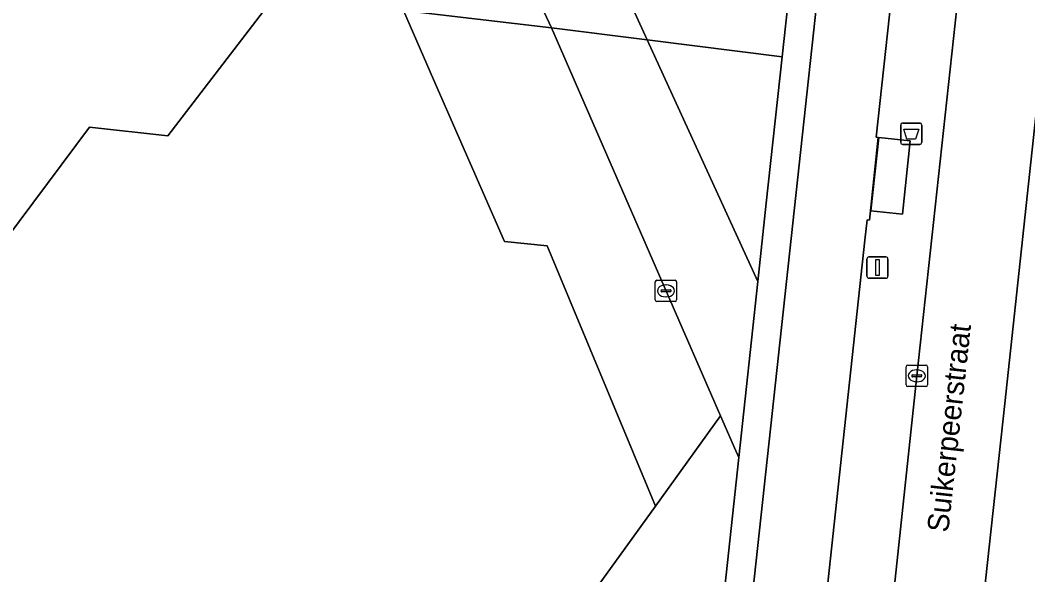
# Model space of a CAD drawing. Extents: x 162026 to 163502, y 387295 to 388169.
# Drawn here: x 162307.77 to 162355.04, y 387456.66 to 387482.7 of the extents above; entities that cross this region are included whole.
import ezdxf

# ---------------------------------------------------------------- set-up
doc = ezdxf.new("R2010")
doc.units = 0
for name, color, linetype in [('IMGEO_Afvalbak', 7, 'Continuous'), ('IMGEO_Berm_groen', 7, 'Continuous'), ('IMGEO_Erf', 7, 'Continuous'), ('IMGEO_Fietspad_gesloten', 7, 'Continuous'), ('IMGEO_Kolk', 7, 'Continuous'), ('IMGEO_Lichtmast', 7, 'Continuous'), ('IMGEO_Openbare_ruimte_label', 7, 'Continuous'), ('IMGEO_Pand', 7, 'Continuous'), ('IMGEO_Rijbaan_lokaal_gesloten', 7, 'Continuous'), ('IMGEO_Rijbaan_lokaal_open', 7, 'Continuous'), ('IMGEO_Voetpad_open', 7, 'Continuous')]:
    doc.layers.add(name, color=color, linetype=linetype)

msp = doc.modelspace()

# ---------------------------------------------------------------- linework, layer by layer
at = {"layer": 'IMGEO_Afvalbak'}
for p, q in [((162349.077, 387476.972), (162349.077, 387477.772)), ((162349.077, 387477.772), (162349.077, 387476.972)), ((162349.177, 387477.872), (162349.967, 387477.872)), ((162349.967, 387477.872), (162349.177, 387477.872)), ((162350.067, 387477.772), (162350.067, 387476.972)), ((162350.067, 387476.972), (162350.067, 387477.772)), ((162349.967, 387476.872), (162349.177, 387476.872)), ((162349.177, 387476.872), (162349.967, 387476.872))]:
    msp.add_line(p, q, dxfattribs=at)
msp.add_lwpolyline([(162349.22, 387477.586), (162349.924, 387477.586), (162349.775, 387477.116), (162349.369, 387477.116), (162349.22, 387477.586)], dxfattribs=at)
for centre, start, end in [((162349.177, 387477.772), 90, 180), ((162349.177, 387477.772), 90, 180), ((162349.967, 387477.772), 0, 90), ((162349.967, 387477.772), 360, 90), ((162349.177, 387476.972), 180, 270), ((162349.177, 387476.972), 180, 270), ((162349.967, 387476.972), 270, 0), ((162349.967, 387476.972), 270, 0)]:
    msp.add_arc(centre, 0.1, start, end, dxfattribs=at)
at = {"layer": 'IMGEO_Berm_groen'}
for points in [[(162367.963, 387504.443), (162368.74, 387511.448), (162359.196, 387512.511), (162358.952, 387511.213), (162358.817, 387510.216), (162358.349, 387505.53), (162353.961, 387464.714), (162349.86, 387427.109)], [(162335.741, 387484.94), (162337.187, 387481.776), (162343.514, 387480.982), (162344.456, 387489.614)]]:
    msp.add_lwpolyline(points, dxfattribs=at)
msp.add_lwpolyline([(162343.514, 387480.982), (162337.187, 387481.776), (162342.369, 387470.441), (162342.765, 387474.112)], close=True, dxfattribs=at)
at = {"layer": 'IMGEO_Erf'}
msp.add_lwpolyline([(162332.69, 387482.34), (162325.748, 387483.156), (162327.164, 387479.918), (162330.488, 387472.319), (162332.494, 387472.101), (162337.569, 387459.89), (162340.618, 387464.132)], close=True, dxfattribs=at)
at = {"layer": 'IMGEO_Fietspad_gesloten'}
msp.add_lwpolyline([(162346.258, 387493.792), (162342.37, 387458.038), (162338.712, 387424.373), (162342.502, 387427.016), (162347.393, 387472.381), (162347.51, 387473.321), (162347.617, 387473.315), (162348.021, 387477.193), (162347.927, 387477.213), (162350.067, 387496.885), (162350.106, 387497.113)], dxfattribs=at)
at = {"layer": 'IMGEO_Kolk'}
for p, q in [((162337.566, 387469.568), (162337.566, 387470.42)), ((162337.641, 387470.494), (162338.493, 387470.494)), ((162337.868, 387470.037), (162338.266, 387470.037)), ((162338.054, 387470.274), (162338.079, 387470.274)), ((162338.567, 387470.42), (162338.567, 387469.568)), ((162337.825, 387469.988), (162337.825, 387470)), ((162338.263, 387469.951), (162337.865, 387469.951)), ((162338.077, 387469.714), (162338.052, 387469.714)), ((162338.309, 387470), (162338.309, 387469.988)), ((162338.493, 387469.494), (162337.641, 387469.494)), ((162349.333, 387465.58), (162349.333, 387466.432)), ((162349.408, 387466.506), (162350.26, 387466.506)), ((162349.821, 387466.286), (162349.846, 387466.286)), ((162350.334, 387466.432), (162350.334, 387465.58)), ((162349.592, 387466), (162349.592, 387466.012)), ((162350.03, 387465.963), (162349.632, 387465.963)), ((162349.635, 387466.049), (162350.033, 387466.049)), ((162350.076, 387466.012), (162350.076, 387466)), ((162350.26, 387465.506), (162349.408, 387465.506)), ((162349.844, 387465.726), (162349.819, 387465.726))]:
    msp.add_line(p, q, dxfattribs=at)
for points in [[(162337.566, 387469.568), (162337.566, 387470.42)], [(162337.641, 387470.494), (162338.493, 387470.494)], [(162338.567, 387470.42), (162338.567, 387469.568)], [(162338.493, 387469.494), (162337.641, 387469.494)], [(162349.333, 387465.58), (162349.333, 387466.432)], [(162349.408, 387466.506), (162350.26, 387466.506)], [(162350.334, 387466.432), (162350.334, 387465.58)], [(162350.26, 387465.506), (162349.408, 387465.506)]]:
    msp.add_lwpolyline(points, dxfattribs=at)
for centre, radius, start, end in [((162337.643, 387470.418), 0.0765, 91.552, 178.448), ((162337.643, 387470.418), 0.0765, 91.552, 178.448), ((162337.865, 387469.997), 0.0403, 85.8775, 175.7526), ((162338.27, 387469.999), 0.0386, 1.7309, 96.639), ((162338.491, 387470.418), 0.0765, 1.552, 88.448), ((162338.491, 387470.418), 0.0765, 1.552, 88.448), ((162337.643, 387469.57), 0.0765, 181.552, 268.448), ((162337.643, 387469.57), 0.0765, 181.552, 268.448), ((162337.862, 387469.987), 0.0366, 178.938, 274.7102), ((162338.266, 387469.994), 0.043, 264.8664, 352.4533), ((162338.491, 387469.57), 0.0765, 271.552, 358.448), ((162338.491, 387469.57), 0.0765, 271.552, 358.448), ((162349.41, 387466.43), 0.0765, 91.552, 178.448), ((162349.41, 387466.43), 0.0765, 91.552, 178.448), ((162350.258, 387466.43), 0.0765, 1.552, 88.448), ((162350.258, 387466.43), 0.0765, 1.552, 88.448), ((162349.632, 387466.009), 0.0403, 85.8775, 175.7526), ((162349.629, 387465.999), 0.0366, 178.938, 274.7102), ((162350.033, 387466.006), 0.043, 264.8664, 352.4533), ((162350.037, 387466.011), 0.0386, 1.7309, 96.639), ((162349.41, 387465.582), 0.0765, 181.552, 268.448), ((162349.41, 387465.582), 0.0765, 181.552, 268.448), ((162350.258, 387465.582), 0.0765, 271.552, 358.448), ((162350.258, 387465.582), 0.0765, 271.552, 358.448)]:
    msp.add_arc(centre, radius, start, end, dxfattribs=at)
for centre, major_axis, ratio, start_param, end_param in [((162338.053, 387469.994), (-0.387, 0.002), 0.722429, 4.712389, 7.853982), ((162338.078, 387469.994), (-0.39, 0.002), 0.717154, 1.570796, 4.712389), ((162349.82, 387466.006), (-0.387, 0.002), 0.722429, 4.712389, 7.853982), ((162349.845, 387466.006), (-0.39, 0.002), 0.717154, 1.570796, 4.712389)]:
    msp.add_ellipse(centre, major_axis=major_axis, ratio=ratio, start_param=start_param, end_param=end_param, dxfattribs=at)
at = {"layer": 'IMGEO_Lichtmast'}
for p, q in [((162347.489, 387470.686), (162347.489, 387471.486)), ((162347.489, 387471.486), (162347.489, 387470.686)), ((162347.589, 387471.586), (162348.379, 387471.586)), ((162348.379, 387471.586), (162347.589, 387471.586)), ((162348.479, 387471.486), (162348.479, 387470.686)), ((162348.479, 387470.686), (162348.479, 387471.486)), ((162348.379, 387470.586), (162347.589, 387470.586)), ((162347.589, 387470.586), (162348.379, 387470.586))]:
    msp.add_line(p, q, dxfattribs=at)
msp.add_lwpolyline([(162347.909, 387471.461), (162348.059, 387471.461), (162348.059, 387470.711), (162347.909, 387470.711), (162347.909, 387471.461)], dxfattribs=at)
for centre, start, end in [((162347.589, 387471.486), 90, 180), ((162347.589, 387471.486), 90, 180), ((162348.379, 387471.486), 0, 90), ((162348.379, 387471.486), 360, 90), ((162347.589, 387470.686), 180, 270), ((162347.589, 387470.686), 180, 270), ((162348.379, 387470.686), 270, 0), ((162348.379, 387470.686), 270, 0)]:
    msp.add_arc(centre, 0.1, start, end, dxfattribs=at)
at = {"layer": 'IMGEO_Pand'}
msp.add_lwpolyline([(162334.245, 387455.266), (162337.569, 387459.89), (162332.494, 387472.101), (162330.488, 387472.319), (162327.164, 387479.918), (162325.748, 387483.156), (162319.71, 387483.814), (162314.702, 387477.278), (162311.025, 387477.679), (162303.078, 387467.032)], dxfattribs=at)
at = {"layer": 'IMGEO_Rijbaan_lokaal_gesloten'}
msp.add_lwpolyline([(162353.961, 387464.714), (162358.349, 387505.53), (162354.15, 387506.017), (162353.924, 387503.81), (162353.243, 387497.608), (162353.136, 387496.605), (162352.335, 387489.102), (162352.257, 387488.34), (162349.834, 387466.006), (162349.065, 387458.811), (162348.272, 387451.322), (162348.127, 387450.097), (162347.103, 387440.899), (162346.475, 387434.916), (162346.314, 387433.695), (162345.649, 387427.488), (162345.245, 387423.574), (162349.464, 387424), (162349.86, 387427.109)], close=True, dxfattribs=at)
at = {"layer": 'IMGEO_Rijbaan_lokaal_open'}
msp.add_lwpolyline([(162332.51, 387496.328), (162331.324, 387494.702), (162329.045, 387491.322), (162328.998, 387491.247), (162328.958, 387491.169), (162328.925, 387491.087), (162328.9, 387491.003), (162328.882, 387490.916), (162328.873, 387490.829), (162328.87, 387490.741), (162328.876, 387490.653), (162328.89, 387490.566), (162328.911, 387490.481), (162328.94, 387490.397), (162328.96, 387490.351), (162329.102, 387490.046), (162330.706, 387486.601), (162332.69, 387482.34), (162337.187, 387481.776), (162335.741, 387484.94)], dxfattribs=at)
msp.add_lwpolyline([(162337.187, 387481.776), (162332.69, 387482.34), (162340.618, 387464.132), (162341.336, 387462.483), (162341.478, 387462.168), (162342.369, 387470.441)], close=True, dxfattribs=at)
at = {"layer": 'IMGEO_Voetpad_open'}
for points in [[(162342.851, 387499.633), (162315.859, 387502.639), (162318.177, 387500), (162320.407, 387497.461), (162310.872, 387484.483), (162310.539, 387484.029), (162298.229, 387485.888), (162293.758, 387496.206), (162291.762, 387495.313), (162289.996, 387490.573), (162287.708, 387487.29), (162294.112, 387472.505), (162292.215, 387469.541), (162293.144, 387466.992), (162297.036, 387466.568), (162297.706, 387467.617), (162303.078, 387467.032), (162311.025, 387477.679), (162314.702, 387477.278), (162319.71, 387483.814), (162325.748, 387483.156), (162332.69, 387482.34), (162330.706, 387486.601), (162329.102, 387490.046)], [(162349.834, 387466.006), (162352.257, 387488.34), (162352.335, 387489.102), (162351.811, 387489.16), (162352.621, 387496.667), (162350.377, 387496.927), (162350.395, 387497.085), (162350.106, 387497.113), (162350.067, 387496.885), (162347.927, 387477.213), (162348.021, 387477.193), (162347.617, 387473.315), (162347.51, 387473.321), (162347.393, 387472.381), (162342.502, 387427.016)], [(162345.131, 387495.972), (162345.114, 387495.816), (162344.697, 387491.886), (162344.694, 387491.855), (162344.456, 387489.614), (162343.514, 387480.982), (162342.765, 387474.112), (162342.369, 387470.441), (162341.478, 387462.168), (162339.151, 387440.575), (162336.896, 387440.801), (162336.777, 387440.813), (162336.313, 387436.552), (162336.266, 387436.121), (162335.062, 387425.067), (162338.712, 387424.373), (162342.37, 387458.038)], [(162342.37, 387458.038), (162346.258, 387493.792)], [(162345.245, 387423.574), (162345.649, 387427.488), (162346.314, 387433.695), (162346.475, 387434.916), (162347.103, 387440.899), (162348.127, 387450.097), (162348.272, 387451.322), (162349.065, 387458.811), (162349.834, 387466.006)]]:
    msp.add_lwpolyline(points, dxfattribs=at)
for points in [[(162347.681, 387473.755), (162348.048, 387477.19), (162349.518, 387477.033), (162349.159, 387473.597)], [(162349.518, 387477.033), (162348.048, 387477.19), (162347.681, 387473.755), (162349.159, 387473.597)], [(162341.478, 387462.168), (162341.336, 387462.483), (162340.618, 387464.132), (162337.569, 387459.89), (162334.245, 387455.266), (162333.93, 387454.828), (162330.754, 387450.41), (162327.944, 387446.501), (162327.884, 387445.951), (162333.026, 387445.391), (162337.225, 387444.932), (162337.182, 387444.535), (162336.777, 387440.813), (162336.896, 387440.801), (162339.151, 387440.575)]]:
    msp.add_lwpolyline(points, close=True, dxfattribs=at)

# ---------------------------------------------------------------- texts
at = {"layer": 'IMGEO_Openbare_ruimte_label'}
msp.add_text('Suikerpeerstraat', height=1, rotation=83.7421, dxfattribs=at).set_placement((162351.306, 387458.625))

doc.saveas('drawing.dxf')
